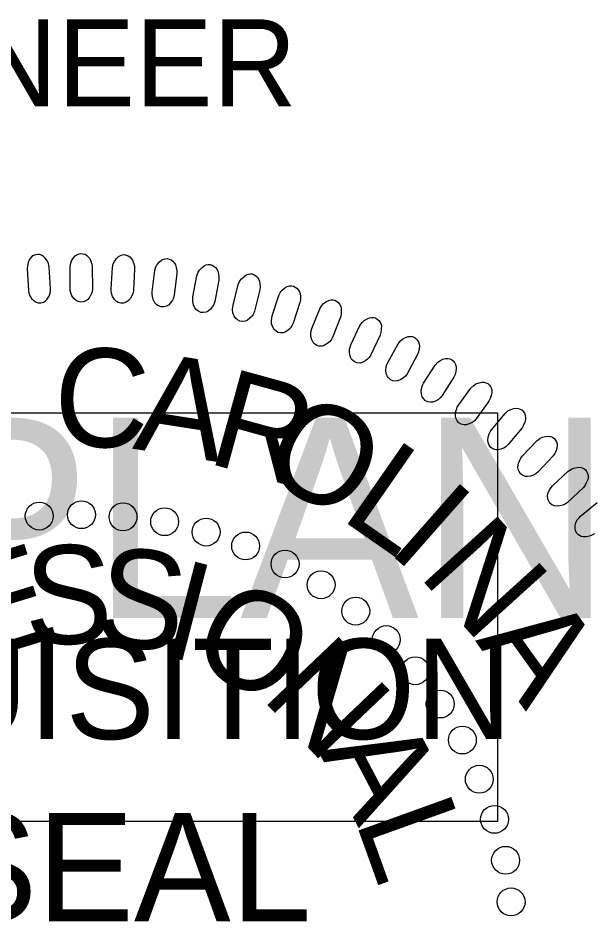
# Model space of a CAD drawing. Extents: x 505602 to 507286, y 483109 to 484209.
# Drawn here: x 507215 to 507248.1, y 484096.7 to 484148.7 of the extents above; entities that cross this region are included whole.
import ezdxf

# ---------------------------------------------------------------- set-up
doc = ezdxf.new("R2010")
doc.units = 0
for name, color, linetype in [('Sheet PE Seal Cell', 7, 'Continuous'), ('Sheet Profile CELL', 7, 'Continuous'), ('Sheet Sticker Incomplete CELL', 7, 'Continuous')]:
    doc.layers.add(name, color=color, linetype=linetype)

msp = doc.modelspace()

# ---------------------------------------------------------------- linework, layer by layer
at = {"layer": 'Sheet PE Seal Cell'}
for points in [[(507218.035, 484133.164), (507218.035, 484134.391), (507218.073, 484134.61), (507218.126, 484134.751), (507218.238, 484134.92), (507218.335, 484135.03), (507218.447, 484135.109), (507218.551, 484135.149), (507218.664, 484135.169), (507218.776, 484135.149), (507218.896, 484135.119), (507219, 484135.059), (507219.105, 484134.959), (507219.165, 484134.879), (507219.232, 484134.73), (507219.292, 484134.55), (507219.314, 484134.391), (507219.321, 484133.134), (507219.299, 484132.965), (507219.253, 484132.825), (507219.164, 484132.666), (507219.052, 484132.525), (507218.954, 484132.446), (507218.797, 484132.386), (507218.648, 484132.367), (507218.499, 484132.406), (507218.394, 484132.456), (507218.266, 484132.556), (507218.147, 484132.726), (507218.08, 484132.905), (507218.05, 484133.035)], [(507216.92, 484133.155), (507216.843, 484134.38), (507216.792, 484134.597), (507216.731, 484134.732), (507216.609, 484134.895), (507216.505, 484134.998), (507216.388, 484135.071), (507216.281, 484135.104), (507216.168, 484135.117), (507216.057, 484135.09), (507215.94, 484135.053), (507215.839, 484134.987), (507215.741, 484134.88), (507215.687, 484134.797), (507215.628, 484134.643), (507215.58, 484134.461), (507215.568, 484134.3), (507215.639, 484133.045), (507215.671, 484132.878), (507215.725, 484132.741), (507215.824, 484132.587), (507215.945, 484132.455), (507216.047, 484132.381), (507216.208, 484132.331), (507216.358, 484132.321), (507216.505, 484132.37), (507216.606, 484132.427), (507216.727, 484132.534), (507216.835, 484132.711), (507216.891, 484132.894), (507216.913, 484133.025)], [(507220.394, 484133.138), (507220.472, 484134.362), (507220.522, 484134.579), (507220.584, 484134.715), (507220.707, 484134.877), (507220.81, 484134.98), (507220.927, 484135.053), (507221.034, 484135.086), (507221.148, 484135.099), (507221.258, 484135.072), (507221.376, 484135.035), (507221.476, 484134.968), (507221.575, 484134.862), (507221.629, 484134.779), (507221.687, 484134.625), (507221.735, 484134.442), (507221.748, 484134.282), (507221.675, 484133.027), (507221.643, 484132.859), (507221.589, 484132.723), (507221.489, 484132.569), (507221.369, 484132.437), (507221.267, 484132.363), (507221.106, 484132.313), (507220.955, 484132.303), (507220.809, 484132.352), (507220.708, 484132.409), (507220.587, 484132.516), (507220.479, 484132.693), (507220.423, 484132.876), (507220.401, 484133.008)], [(507222.757, 484132.963), (507222.911, 484134.18), (507222.975, 484134.393), (507223.045, 484134.524), (507223.177, 484134.679), (507223.288, 484134.776), (507223.409, 484134.84), (507223.518, 484134.867), (507223.631, 484134.873), (507223.74, 484134.838), (507223.855, 484134.794), (507223.951, 484134.722), (507224.043, 484134.609), (507224.092, 484134.523), (507224.141, 484134.366), (507224.176, 484134.18), (507224.179, 484134.019), (507224.028, 484132.771), (507223.985, 484132.606), (507223.923, 484132.474), (507223.814, 484132.326), (507223.685, 484132.202), (507223.579, 484132.135), (507223.415, 484132.095), (507223.265, 484132.094), (507223.121, 484132.153), (507223.024, 484132.215), (507222.91, 484132.33), (507222.812, 484132.513), (507222.769, 484132.7), (507222.755, 484132.833)], [(507225.096, 484132.677), (507225.326, 484133.881), (507225.404, 484134.09), (507225.482, 484134.217), (507225.624, 484134.362), (507225.74, 484134.452), (507225.865, 484134.509), (507225.975, 484134.529), (507226.089, 484134.528), (507226.195, 484134.487), (507226.307, 484134.435), (507226.399, 484134.356), (507226.483, 484134.239), (507226.527, 484134.15), (507226.565, 484133.99), (507226.59, 484133.802), (507226.582, 484133.641), (507226.354, 484132.405), (507226.299, 484132.243), (507226.229, 484132.115), (507226.111, 484131.975), (507225.975, 484131.859), (507225.864, 484131.798), (507225.699, 484131.769), (507225.548, 484131.778), (507225.409, 484131.845), (507225.316, 484131.913), (507225.21, 484132.035), (507225.124, 484132.224), (507225.091, 484132.413), (507225.087, 484132.546)], [(507227.402, 484132.203), (507227.707, 484133.391), (507227.797, 484133.593), (507227.883, 484133.716), (507228.034, 484133.853), (507228.155, 484133.934), (507228.284, 484133.984), (507228.395, 484133.996), (507228.509, 484133.988), (507228.612, 484133.941), (507228.721, 484133.882), (507228.807, 484133.798), (507228.883, 484133.675), (507228.922, 484133.583), (507228.949, 484133.421), (507228.963, 484133.233), (507228.945, 484133.072), (507228.639, 484131.853), (507228.575, 484131.695), (507228.496, 484131.571), (507228.37, 484131.439), (507228.227, 484131.331), (507228.113, 484131.278), (507227.946, 484131.259), (507227.796, 484131.277), (507227.662, 484131.354), (507227.573, 484131.428), (507227.474, 484131.556), (507227.4, 484131.75), (507227.38, 484131.94), (507227.383, 484132.073)], [(507229.651, 484131.581), (507230.031, 484132.747), (507230.134, 484132.945), (507230.227, 484133.061), (507230.386, 484133.188), (507230.513, 484133.261), (507230.644, 484133.303), (507230.756, 484133.308), (507230.869, 484133.293), (507230.969, 484133.239), (507231.073, 484133.173), (507231.155, 484133.084), (507231.223, 484132.957), (507231.255, 484132.863), (507231.273, 484132.7), (507231.274, 484132.51), (507231.247, 484132.352), (507230.865, 484131.155), (507230.791, 484131), (507230.705, 484130.881), (507230.571, 484130.757), (507230.42, 484130.659), (507230.304, 484130.613), (507230.136, 484130.605), (507229.987, 484130.633), (507229.858, 484130.717), (507229.774, 484130.796), (507229.684, 484130.93), (507229.622, 484131.128), (507229.614, 484131.32), (507229.626, 484131.453)], [(507231.935, 484130.846), (507232.387, 484131.986), (507232.502, 484132.176), (507232.602, 484132.287), (507232.769, 484132.403), (507232.9, 484132.469), (507233.034, 484132.502), (507233.145, 484132.501), (507233.257, 484132.478), (507233.353, 484132.418), (507233.454, 484132.346), (507233.529, 484132.252), (507233.59, 484132.121), (507233.616, 484132.024), (507233.624, 484131.861), (507233.613, 484131.672), (507233.575, 484131.515), (507233.119, 484130.344), (507233.035, 484130.195), (507232.942, 484130.081), (507232.8, 484129.967), (507232.645, 484129.877), (507232.525, 484129.839), (507232.357, 484129.842), (507232.211, 484129.879), (507232.086, 484129.97), (507232.007, 484130.055), (507231.926, 484130.195), (507231.878, 484130.397), (507231.881, 484130.588), (507231.901, 484130.72)], [(507234.176, 484129.912), (507234.699, 484131.021), (507234.826, 484131.204), (507234.933, 484131.308), (507235.107, 484131.414), (507235.241, 484131.472), (507235.376, 484131.496), (507235.488, 484131.487), (507235.598, 484131.458), (507235.691, 484131.391), (507235.787, 484131.314), (507235.856, 484131.215), (507235.908, 484131.08), (507235.928, 484130.983), (507235.925, 484130.818), (507235.903, 484130.631), (507235.855, 484130.476), (507235.326, 484129.337), (507235.234, 484129.193), (507235.134, 484129.085), (507234.984, 484128.979), (507234.824, 484128.901), (507234.701, 484128.87), (507234.534, 484128.883), (507234.39, 484128.929), (507234.273, 484129.028), (507234.199, 484129.118), (507234.126, 484129.262), (507234.091, 484129.466), (507234.106, 484129.658), (507234.134, 484129.787)], [(507236.3, 484128.896), (507236.891, 484129.971), (507237.03, 484130.145), (507237.143, 484130.242), (507237.323, 484130.337), (507237.461, 484130.386), (507237.598, 484130.402), (507237.709, 484130.387), (507237.816, 484130.35), (507237.905, 484130.278), (507237.995, 484130.194), (507238.058, 484130.092), (507238.102, 484129.954), (507238.116, 484129.855), (507238.103, 484129.692), (507238.068, 484129.505), (507238.012, 484129.355), (507237.412, 484128.25), (507237.311, 484128.113), (507237.204, 484128.012), (507237.049, 484127.915), (507236.883, 484127.847), (507236.759, 484127.824), (507236.593, 484127.847), (507236.452, 484127.902), (507236.34, 484128.009), (507236.273, 484128.103), (507236.21, 484128.252), (507236.187, 484128.458), (507236.214, 484128.647), (507236.25, 484128.776)], [(507238.358, 484127.711), (507239.016, 484128.747), (507239.165, 484128.912), (507239.284, 484129.002), (507239.469, 484129.085), (507239.61, 484129.126), (507239.748, 484129.133), (507239.857, 484129.11), (507239.963, 484129.067), (507240.047, 484128.99), (507240.131, 484128.9), (507240.188, 484128.794), (507240.223, 484128.654), (507240.23, 484128.554), (507240.207, 484128.391), (507240.161, 484128.208), (507240.095, 484128.062), (507239.427, 484126.997), (507239.317, 484126.866), (507239.205, 484126.772), (507239.044, 484126.685), (507238.874, 484126.627), (507238.749, 484126.612), (507238.584, 484126.646), (507238.448, 484126.709), (507238.343, 484126.823), (507238.281, 484126.922), (507238.227, 484127.074), (507238.218, 484127.281), (507238.257, 484127.468), (507238.301, 484127.594)], [(507240.358, 484126.438), (507241.079, 484127.43), (507241.238, 484127.586), (507241.363, 484127.668), (507241.553, 484127.739), (507241.696, 484127.771), (507241.834, 484127.77), (507241.942, 484127.74), (507242.045, 484127.69), (507242.124, 484127.609), (507242.202, 484127.514), (507242.252, 484127.404), (507242.278, 484127.262), (507242.28, 484127.162), (507242.246, 484127.001), (507242.189, 484126.821), (507242.113, 484126.679), (507241.38, 484125.658), (507241.262, 484125.534), (507241.144, 484125.448), (507240.978, 484125.371), (507240.805, 484125.324), (507240.679, 484125.317), (507240.517, 484125.361), (507240.385, 484125.433), (507240.287, 484125.553), (507240.232, 484125.655), (507240.187, 484125.81), (507240.191, 484126.017), (507240.242, 484126.202), (507240.294, 484126.325)], [(507242.252, 484125.022), (507243.035, 484125.967), (507243.203, 484126.112), (507243.332, 484126.186), (507243.527, 484126.246), (507243.672, 484126.268), (507243.809, 484126.258), (507243.915, 484126.222), (507244.014, 484126.165), (507244.088, 484126.079), (507244.161, 484125.979), (507244.203, 484125.867), (507244.22, 484125.723), (507244.216, 484125.624), (507244.172, 484125.466), (507244.104, 484125.289), (507244.02, 484125.152), (507243.224, 484124.179), (507243.098, 484124.063), (507242.974, 484123.984), (507242.804, 484123.918), (507242.628, 484123.882), (507242.502, 484123.882), (507242.343, 484123.936), (507242.216, 484124.017), (507242.126, 484124.143), (507242.077, 484124.248), (507242.043, 484124.406), (507242.059, 484124.612), (507242.122, 484124.794), (507242.182, 484124.913)], [(507244.024, 484123.508), (507244.864, 484124.402), (507245.041, 484124.536), (507245.175, 484124.602), (507245.373, 484124.649), (507245.519, 484124.663), (507245.655, 484124.644), (507245.759, 484124.601), (507245.855, 484124.539), (507245.922, 484124.448), (507245.989, 484124.344), (507246.025, 484124.229), (507246.032, 484124.084), (507246.022, 484123.985), (507245.968, 484123.83), (507245.889, 484123.658), (507245.796, 484123.527), (507244.94, 484122.606), (507244.808, 484122.498), (507244.68, 484122.427), (507244.505, 484122.372), (507244.328, 484122.347), (507244.202, 484122.355), (507244.047, 484122.419), (507243.924, 484122.507), (507243.843, 484122.639), (507243.801, 484122.746), (507243.776, 484122.906), (507243.805, 484123.112), (507243.879, 484123.288), (507243.946, 484123.403)], [(507245.768, 484121.814), (507246.663, 484122.654), (507246.848, 484122.776), (507246.986, 484122.834), (507247.186, 484122.869), (507247.333, 484122.873), (507247.467, 484122.846), (507247.569, 484122.797), (507247.66, 484122.729), (507247.722, 484122.633), (507247.782, 484122.525), (507247.81, 484122.408), (507247.809, 484122.264), (507247.791, 484122.165), (507247.728, 484122.014), (507247.639, 484121.848), (507247.538, 484121.722), (507246.626, 484120.857), (507246.487, 484120.757), (507246.355, 484120.694), (507246.178, 484120.65), (507245.999, 484120.637), (507245.874, 484120.653), (507245.723, 484120.726), (507245.606, 484120.822), (507245.533, 484120.958), (507245.498, 484121.068), (507245.483, 484121.229), (507245.525, 484121.432), (507245.61, 484121.605), (507245.684, 484121.715)]]:
    msp.add_lwpolyline(points, close=True, dxfattribs=at)
msp.add_lwpolyline([(507248.177, 484119.058), (507248.032, 484118.968), (507247.895, 484118.913), (507247.715, 484118.881), (507247.536, 484118.878), (507247.413, 484118.902), (507247.266, 484118.985), (507247.156, 484119.088), (507247.092, 484119.228), (507247.063, 484119.34), (507247.059, 484119.502), (507247.114, 484119.702), (507247.209, 484119.869), (507247.29, 484119.974), (507247.38, 484120.068), (507248.326, 484120.85)], dxfattribs=at)
for centre in [(507216.263, 484120.069), (507218.692, 484120.148), (507221.081, 484120.027), (507223.47, 484119.748), (507225.858, 484119.149), (507228.127, 484118.352), (507230.396, 484117.315), (507232.466, 484116.12), (507234.456, 484114.605), (507236.208, 484112.971), (507237.879, 484111.178), (507239.312, 484109.265), (507240.585, 484107.194), (507241.557, 484104.944), (507242.432, 484102.633), (507243.069, 484100.283), (507243.386, 484097.892)]:
    msp.add_circle(centre, 0.801, dxfattribs=at)
at = {"layer": 'Sheet Sticker Incomplete CELL'}
msp.add_lwpolyline([(507095.597, 484102.505), (507095.597, 484126.005), (507242.597, 484126.005), (507242.597, 484102.505)], close=True, dxfattribs=at)

# ---------------------------------------------------------------- texts
at = {"layer": 'Sheet PE Seal Cell'}
for s, height, rotation, p in [('C', 5.669, 357.5877, (507217.01, 484124.159)), ('A', 5.669, 351.0983, (507221.585, 484123.951)), ('R', 5.669, 344.609, (507225.792, 484123.156)), ('O', 5.669, 331.6302, (507228.747, 484122.502)), ('L', 5.669, 325.1409, (507233.48, 484119.971)), ('I', 5.669, 318.6515, (507236.173, 484118.118)), ('N', 5.669, 312.1622, (507237.978, 484116.698)), ('E', 5.669, 17.1686, (507212.701, 484111.706)), ('S', 5.669, 1.289, (507215.468, 484112.666)), ('S', 5.669, 353.3492, (507219.329, 484112.767)), ('I', 5.669, 345.4094, (507223.13, 484112.136)), ('O', 5.669, 329.5298, (507224.633, 484111.964)), ('A', 5.669, 305.6728, (507241.298, 484112.918)), ('N', 5.669, 313.6502, (507228.945, 484109.66)), ('A', 5.669, 297.7707, (507232.282, 484106.579)), ('L', 5.669, 289.8309, (507234.406, 484102.584)), ('SEAL', 6.2363, 359.9814, (507210.585, 484096.772))]:
    msp.add_text(s, height=height, rotation=rotation, dxfattribs=at).set_placement(p)
at = {"layer": 'Sheet Profile CELL'}
msp.add_text('ENGINEER', height=5.0001, dxfattribs=at).set_placement((507196.142, 484143.624))
at = {"layer": 'Sheet Sticker Incomplete CELL'}
for s, height, p in [('INCOMPLETE PLANS', 11.52, (507104.547, 484114.205)), ('DO NOT USE FOR R/W ACQUISITION', 5.76, (507107.797, 484107.255))]:
    msp.add_text(s, height=height, dxfattribs=at).set_placement(p)

doc.saveas('drawing.dxf')
